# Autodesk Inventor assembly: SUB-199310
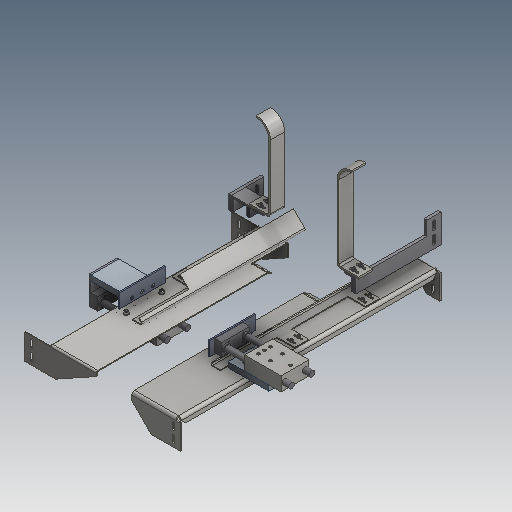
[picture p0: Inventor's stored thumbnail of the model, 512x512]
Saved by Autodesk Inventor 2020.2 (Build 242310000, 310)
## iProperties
Created: 2000-01
Part Number: SUB-199310
Document SubType Name: Assembly
Designer: sspink
Mass: 14809.9 g
Surface Area: 15496.4 cm^2
Volume: 4664.4 cm^3
Density: 3.17509 g/cm^3
Control State: 0
Checked Out: False
Master: False
Shininess: 0.0
Length Units: 11269
Angle Units: 11279
Time Units: 11290
Mass Units: 11283
Length Display Precision: 3
Angle Display Precision: 2
Compacted: True
Dimensions: 497x985,5x717,4 mm
Mass: 14,81 kg
DocNumber: SUB-199310.iam
Folder: 01 - Themengebiete\Simplification\01 - Packaging machine\
VDS_Category: 3D Komponenten
Density: 0.0
Volumn: 0.0
Area: 0.0
PropertySet Name: Model Information
Author: sspink
Revision Number: -
Title: SUB-199310
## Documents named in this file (29)
- D:\07 - DEMODATEN\OTX 2019 - Dataset - UPDATE - Dez2019\Designs\07-Packing machine\SUB-199310.iam
- D:\07 - DEMODATEN\OTX 2019 - Dataset - UPDATE - Dez2019\Designs\07-Packing machine\A102253.iam
- D:\07 - DEMODATEN\OTX 2019 - Dataset - UPDATE - Dez2019\Designs\07-Packing machine\500569R.iam
- D:\07 - DEMODATEN\OTX 2019 - Dataset - UPDATE - Dez2019\Designs\07-Packing machine\Parts\ADSK-011485.ipt
- D:\07 - DEMODATEN\OTX 2019 - Dataset - UPDATE - Dez2019\Designs\07-Packing machine\Parts\ADSK-011486.ipt
- D:\07 - DEMODATEN\OTX 2019 - Dataset - UPDATE - Dez2019\Designs\07-Packing machine\500570R.iam
- D:\07 - DEMODATEN\OTX 2019 - Dataset - UPDATE - Dez2019\Designs\07-Packing machine\Parts\ADSK-011505.ipt
- D:\07 - DEMODATEN\OTX 2019 - Dataset - UPDATE - Dez2019\Designs\07-Packing machine\Parts\ADSK-011489.ipt
- D:\07 - DEMODATEN\OTX 2019 - Dataset - UPDATE - Dez2019\Designs\07-Packing machine\Parts\ADSK-011492.ipt
- D:\07 - DEMODATEN\OTX 2019 - Dataset - UPDATE - Dez2019\Designs\07-Packing machine\Parts\ADSK-011494.ipt
- D:\07 - DEMODATEN\OTX 2019 - Dataset - UPDATE - Dez2019\Designs\07-Packing machine\Parts\ADSK-011495.ipt
- D:\07 - DEMODATEN\OTX 2019 - Dataset - UPDATE - Dez2019\Designs\07-Packing machine\Parts\ADSK-011496.ipt
- D:\07 - DEMODATEN\OTX 2019 - Dataset - UPDATE - Dez2019\Designs\07-Packing machine\Parts\ADSK-011497.ipt
- D:\07 - DEMODATEN\OTX 2019 - Dataset - UPDATE - Dez2019\Designs\07-Packing machine\Parts\ADSK-011506.ipt
- D:\07 - DEMODATEN\OTX 2019 - Dataset - UPDATE - Dez2019\Designs\07-Packing machine\Parts\ADSK-011473.ipt
- D:\07 - DEMODATEN\OTX 2019 - Dataset - UPDATE - Dez2019\Designs\07-Packing machine\Parts\ADSK-011402.ipt
- D:\07 - DEMODATEN\OTX 2019 - Dataset - UPDATE - Dez2019\Content Center Files\de-DE\ISO 4762(2)\ISO 4762 - M6 x 60ISO.ipt
- D:\07 - DEMODATEN\OTX 2019 - Dataset - UPDATE - Dez2019\Content Center Files\de-DE\ISO 4762(2)\ISO 4762 - M6 x 50ISO.ipt
- D:\07 - DEMODATEN\OTX 2019 - Dataset - UPDATE - Dez2019\Content Center Files\de-DE\DIN 125-1  B\DIN 125-1 - B 6,4.ipt
- D:\07 - DEMODATEN\OTX 2019 - Dataset - UPDATE - Dez2019\Content Center Files\de-DE\ISO 4762(2)\ISO 4762 - M6 x 20ISO.ipt
- D:\07 - DEMODATEN\OTX 2019 - Dataset - UPDATE - Dez2019\Content Center Files\de-DE\ISO 4762(2)\ISO 4762 - M5 x 20ISO.ipt
- D:\07 - DEMODATEN\OTX 2019 - Dataset - UPDATE - Dez2019\Content Center Files\de-DE\DIN 125-1  B\DIN 125-1 - B 5,3.ipt
- D:\07 - DEMODATEN\OTX 2019 - Dataset - UPDATE - Dez2019\Content Center Files\de-DE\ISO 10642(1)\ISO 10642 - M5x12.ipt
- D:\07 - DEMODATEN\OTX 2019 - Dataset - UPDATE - Dez2019\Content Center Files\de-DE\DIN 125-1  B\DIN 125-1 - B 8,4.ipt
- D:\07 - DEMODATEN\OTX 2019 - Dataset - UPDATE - Dez2019\Content Center Files\de-DE\ISO 4032(1)\ISO 4032 - M8DIN EN.ipt
- D:\07 - DEMODATEN\OTX 2019 - Dataset - UPDATE - Dez2019\Content Center Files\de-DE\ISO 4762(2)\ISO 4762 - M8 x 25ISO.ipt
- D:\07 - DEMODATEN\OTX 2019 - Dataset - UPDATE - Dez2019\Content Center Files\de-DE\ISO 4762(2)\ISO 4762 - M5 x 10ISO.ipt
- D:\07 - DEMODATEN\OTX 2019 - Dataset - UPDATE - Dez2019\Content Center Files\de-DE\ISO 4762(2)\ISO 4762 - M8 x 20ISO.ipt
- D:\07 - DEMODATEN\OTX 2019 - Dataset - UPDATE - Dez2019\Content Center Files\de-DE\ISO 4762(2)\ISO 4762 - M6 x 12ISO.ipt
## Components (80 placed, 28 different names)
1. ADSK-011485:1 — Flush:1, Mate:7, Fluchtend:18, Passend:15, Passend:16, Passend:56, Passend:58, Passend:60, Passend:62
2. ADSK-011486:1 — Flush:1, Fluchtend:19, Mate:10, Passend:13, Passend:14, Passend:64, Passend:66, Passend:68, Passend:70
3. A102253:1 [sub-assembly] — Insert:3, Insert:4, Passend:25, Passend:27, Passend:28, Passend:75
4. A102253:2 [sub-assembly] — Flush:3, Flush:4, Insert:1, Insert:2, Mate:8
5. ADSK-011489:1 — Passend:22, Passend:25, Fluchtend:25, Passend:26, Passend:27, Passend:28
6. ADSK-011492:1 — Flush:3, Flush:4, Mate:8, Mate:9, Flush:14, Passend:17, Passend:18, Passend:48, Passend:50
7. ADSK-011494:1 — Insert:1, Insert:2, Insert:5, Insert:6, Einfügen:22, Einfügen:23
8. ADSK-011495:1 — Insert:3, Insert:4, Passend:75
9. ADSK-011496:1 — Insert:5, Insert:6, Passend:19, Passend:20, Passend:21
10. ADSK-011497:1 — Passend:19, Passend:20, Passend:21
11. 500569R:1 [sub-assembly] — Mate:2, Flush:8, Flush:21, Mate:11, Flush:7, Fluchtend:26
12. 500570R:1 [sub-assembly] — Mate:3, Flush:10, Flush:23, Mate:12, Flush:9, Passend:84
13. ADSK-011505:1 — Mate:2, Flush:8, Flush:7, Passend:77, Passend:79
14. ADSK-011506:1 — Mate:3, Flush:10, Flush:9, Passend:81, Passend:83
15. ADSK-011402:1 — Mate:5, Fluchtend:28, Mate:7, Fluchtend:18, Flush:21, Mate:11, Fluchtend:24, Passend:15, Passend:16, Passend:22, Fluchtend:25, Passend:26, Passend:72, Passend:74, Fluchtend:26, Fluchtend:11
16. ADSK-011473:1 — Fluchtend:11, Fluchtend:27, Flush:12, Mate:9, Flush:14, Fluchtend:19, Mate:10, Flush:23, Mate:12, Fluchtend:24, Passend:13, Passend:14, Passend:17, Passend:18, Passend:52, Passend:54, Passend:84
17. DIN 125-1 B B 5,3:4 — Passend:56
18. DIN 125-1 B B 5,3:5 — Passend:58
19. DIN 125-1 B B 5,3:6 — Passend:60
20. DIN 125-1 B B 5,3:7 — Passend:62
21. ISO 4762 M5 x 10:1
22. ISO 4762 M5 x 10:2
23. ISO 4762 M5 x 10:3
24. ISO 4762 M5 x 10:4
25. DIN 125-1 B B 5,3:8 — Passend:64
26. DIN 125-1 B B 5,3:9 — Passend:66
27. DIN 125-1 B B 5,3:10 — Passend:68
28. DIN 125-1 B B 5,3:11 — Passend:70
29. ISO 4762 M5 x 10:5
30. ISO 4762 M5 x 10:6
31. ISO 4762 M5 x 10:7
32. DIN 125-1 B B 8,4:5 — Passend:72
33. DIN 125-1 B B 8,4:6 — Passend:74
34. ISO 4762 M8 x 20:1
35. ISO 4762 M8 x 20:2
36. DIN 125-1 B B 6,4:8 — Passend:77
37. DIN 125-1 B B 6,4:9 — Passend:79
38. DIN 125-1 B B 6,4:10 — Passend:81
39. DIN 125-1 B B 6,4:11 — Passend:83
40. ISO 4762 M6 x 12:1
41. ISO 4762 M6 x 12:2
42. ISO 4762 M6 x 12:3
43. ISO 4762 M6 x 12:4
44. ISO 4762 M6 x 60:1
45. ISO 4762 M6 x 60:2
46. ISO 4762 M6 x 60:3
47. ISO 4762 M6 x 60:4
48. ISO 4762 M6 x 50:1
49. ISO 4762 M6 x 50:2
50. ISO 4762 M6 x 50:3
51. ISO 4762 M6 x 50:4
52. DIN 125-1 B B 6,4:1 — Passend:30, Passend:32, Passend:34, Passend:36
53. DIN 125-1 B B 5,3:1
54. DIN 125-1 B B 6,4:5
55. DIN 125-1 B B 6,4:6
56. DIN 125-1 B B 6,4:7
57. ISO 4762 M6 x 20:1 — Passend:30
58. ISO 4762 M6 x 20:2 — Passend:32
59. ISO 4762 M6 x 20:3 — Passend:34
60. ISO 4762 M6 x 20:4 — Passend:36
61. ISO 4762 M5 x 20:1
62. ISO 4762 M5 x 20:2 — Einfügen:24
63. DIN 125-1 B B 5,3:2 — Einfügen:22, Einfügen:25
64. ISO 4762 M5 x 20:3 — Einfügen:25
65. DIN 125-1 B B 5,3:3 — Einfügen:23, Einfügen:24
66. ISO 10642 M5x12:1
67. ISO 10642 M5x12:2
68. ISO 10642 M5x12:3
69. ISO 10642 M5x12:4
70. ISO 10642 M5x12:5
71. ISO 10642 M5x12:6
72. ISO 10642 M5x12:7
73. DIN 125-1 B B 8,4:1 — Passend:48
74. DIN 125-1 B B 8,4:2 — Passend:50
75. DIN 125-1 B B 8,4:3 — Passend:52
76. DIN 125-1 B B 8,4:4 — Passend:54
77. DIN EN 24032 M8:1
78. DIN EN 24032 M8:2
79. ISO 4762 M8 x 25:1
80. ISO 4762 M8 x 25:2
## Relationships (76: Mate 47, Flush 19, Insert 10)
- Flush:1: ADSK-011485:1 ↔ ADSK-011486:1
- Flush:3: A102253:2 ↔ ADSK-011492:1
- Flush:4: A102253:2 ↔ ADSK-011492:1
- Insert:1: A102253:2 ↔ ADSK-011494:1
- Insert:2: A102253:2 ↔ ADSK-011494:1
- Insert:3: A102253:1 ↔ ADSK-011495:1
- Insert:4: A102253:1 ↔ ADSK-011495:1
- Insert:5: ADSK-011494:1 ↔ ADSK-011496:1
- Insert:6: ADSK-011494:1 ↔ ADSK-011496:1
- Mate:2: 500569R:1 ↔ ADSK-011505:1
- Flush:8: 500569R:1 ↔ ADSK-011505:1
- Mate:3: 500570R:1 ↔ ADSK-011506:1
- Flush:10: 500570R:1 ↔ ADSK-011506:1
- Fluchtend:11 [Flush]: ADSK-011402:1 ↔ ADSK-011473:1
- Fluchtend:27 [Flush]: ADSK-011473:1
- Flush:12: ADSK-011473:1
- Mate:5: ADSK-011402:1
- Fluchtend:28 [Flush]: ADSK-011402:1
- Mate:7: ADSK-011485:1 ↔ ADSK-011402:1
- Mate:8: A102253:2 ↔ ADSK-011492:1
- Mate:9: ADSK-011492:1 ↔ ADSK-011473:1
- Flush:14: ADSK-011492:1 ↔ ADSK-011473:1
- Fluchtend:18 [Flush]: ADSK-011485:1 ↔ ADSK-011402:1
- Fluchtend:19 [Flush]: ADSK-011486:1 ↔ ADSK-011473:1
- Mate:10: ADSK-011486:1 ↔ ADSK-011473:1
- Flush:21: 500569R:1 ↔ ADSK-011402:1
- Flush:23: 500570R:1 ↔ ADSK-011473:1
- Mate:11: 500569R:1 ↔ ADSK-011402:1
- Mate:12: 500570R:1 ↔ ADSK-011473:1
- Flush:7: 500569R:1 ↔ ADSK-011505:1
- Flush:9: 500570R:1 ↔ ADSK-011506:1
- Fluchtend:24 [Flush]: ADSK-011402:1 ↔ ADSK-011473:1
- Passend:13 [Mate]: ADSK-011486:1 ↔ ADSK-011473:1
- Passend:14 [Mate]: ADSK-011486:1 ↔ ADSK-011473:1
- Passend:15 [Mate]: ADSK-011485:1 ↔ ADSK-011402:1
- Passend:16 [Mate]: ADSK-011485:1 ↔ ADSK-011402:1
- Passend:17 [Mate]: ADSK-011492:1 ↔ ADSK-011473:1
- Passend:18 [Mate]: ADSK-011492:1 ↔ ADSK-011473:1
- Passend:19 [Mate]: ADSK-011496:1 ↔ ADSK-011497:1
- Passend:20 [Mate]: ADSK-011496:1 ↔ ADSK-011497:1
- Passend:21 [Mate]: ADSK-011496:1 ↔ ADSK-011497:1
- Passend:22 [Mate]: ADSK-011489:1 ↔ ADSK-011402:1
- Passend:25 [Mate]: A102253:1 ↔ ADSK-011489:1
- Fluchtend:25 [Flush]: ADSK-011489:1 ↔ ADSK-011402:1
- Passend:26 [Mate]: ADSK-011489:1 ↔ ADSK-011402:1
- Passend:27 [Mate]: A102253:1 ↔ ADSK-011489:1
- Passend:28 [Mate]: A102253:1 ↔ ADSK-011489:1
- Passend:30 [Mate]: DIN 125-1 B B 6,4:1 ↔ ISO 4762 M6 x 20:1
- Passend:32 [Mate]: DIN 125-1 B B 6,4:1 ↔ ISO 4762 M6 x 20:2
- Passend:34 [Mate]: DIN 125-1 B B 6,4:1 ↔ ISO 4762 M6 x 20:3
- Passend:36 [Mate]: DIN 125-1 B B 6,4:1 ↔ ISO 4762 M6 x 20:4
- Einfügen:22 [Insert]: ADSK-011494:1 ↔ DIN 125-1 B B 5,3:2
- Einfügen:23 [Insert]: ADSK-011494:1 ↔ DIN 125-1 B B 5,3:3
- Einfügen:24 [Insert]: ISO 4762 M5 x 20:2 ↔ DIN 125-1 B B 5,3:3
- Einfügen:25 [Insert]: DIN 125-1 B B 5,3:2 ↔ ISO 4762 M5 x 20:3
- Passend:48 [Mate]: ADSK-011492:1 ↔ DIN 125-1 B B 8,4:1
- Passend:50 [Mate]: ADSK-011492:1 ↔ DIN 125-1 B B 8,4:2
- Passend:52 [Mate]: ADSK-011473:1 ↔ DIN 125-1 B B 8,4:3
- Passend:54 [Mate]: ADSK-011473:1 ↔ DIN 125-1 B B 8,4:4
- Passend:56 [Mate]: ADSK-011485:1 ↔ DIN 125-1 B B 5,3:4
- Passend:58 [Mate]: ADSK-011485:1 ↔ DIN 125-1 B B 5,3:5
- Passend:60 [Mate]: ADSK-011485:1 ↔ DIN 125-1 B B 5,3:6
- Passend:62 [Mate]: ADSK-011485:1 ↔ DIN 125-1 B B 5,3:7
- Passend:64 [Mate]: ADSK-011486:1 ↔ DIN 125-1 B B 5,3:8
- Passend:66 [Mate]: ADSK-011486:1 ↔ DIN 125-1 B B 5,3:9
- Passend:68 [Mate]: ADSK-011486:1 ↔ DIN 125-1 B B 5,3:10
- Passend:70 [Mate]: ADSK-011486:1 ↔ DIN 125-1 B B 5,3:11
- Passend:72 [Mate]: ADSK-011402:1 ↔ DIN 125-1 B B 8,4:5
- Passend:74 [Mate]: ADSK-011402:1 ↔ DIN 125-1 B B 8,4:6
- Passend:75 [Mate]: A102253:1 ↔ ADSK-011495:1
- Passend:77 [Mate]: ADSK-011505:1 ↔ DIN 125-1 B B 6,4:8
- Passend:79 [Mate]: ADSK-011505:1 ↔ DIN 125-1 B B 6,4:9
- Passend:81 [Mate]: ADSK-011506:1 ↔ DIN 125-1 B B 6,4:10
- Passend:83 [Mate]: ADSK-011506:1 ↔ DIN 125-1 B B 6,4:11
- Passend:84 [Mate]: 500570R:1 ↔ ADSK-011473:1
- Fluchtend:26 [Flush]: 500569R:1 ↔ ADSK-011402:1
